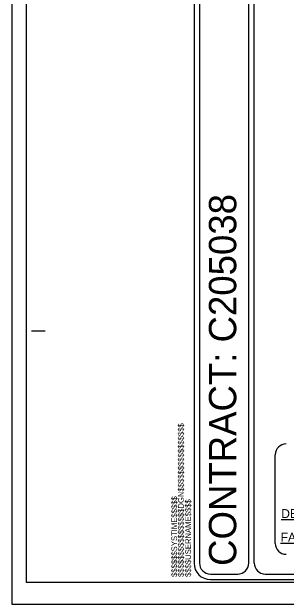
# Model space of a CAD drawing. Extents: x 2046816 to 2049224, y 578750 to 586986.
# Drawn here: x 2047541 to 2047791, y 585891 to 586432 of the extents above; entities that cross this region are included whole.
import ezdxf

# ---------------------------------------------------------------- set-up
doc = ezdxf.new("R2010")
doc.units = 0
for name, color, linetype in [('Sheet Data Field CELL', 7, 'Continuous'), ('Sheet Plan CELL', 7, 'Continuous'), ('Sheet Plot Border Inside CELL', 7, 'Continuous'), ('Sheet Plot Border Outside CELL', 7, 'Continuous'), ('Sheet Title CELL', 7, 'Continuous')]:
    doc.layers.add(name, color=color, linetype=linetype)

msp = doc.modelspace()

# ---------------------------------------------------------------- linework, layer by layer
at = {"layer": 'Sheet Plot Border Inside CELL'}
msp.add_lwpolyline([(2047553.67, 585910.81), (2049219.66, 585910.81), (2049219.66, 586965.81), (2047553.67, 586965.81)], close=True, dxfattribs=at)
at = {"layer": 'Sheet Plot Border Outside CELL'}
msp.add_lwpolyline([(2049224.17, 586985.81), (2047540.67, 586985.81), (2047540.67, 585890.81), (2049224.17, 585890.81)], close=True, dxfattribs=at)
at = {"layer": 'Sheet Title CELL'}
for p, q in [((2047757.16, 585928.33), (2047757.16, 586948.31)), ((2047762.16, 585928.31), (2047762.16, 586948.31)), ((2047558.66, 586140.81), (2047571.16, 586140.83)), ((2047781.37, 585946.39), (2047781.37, 586027.41)), ((2047786.89, 585968.08), (2047942.04, 585968.07)), ((2047786.34, 585946.44), (2047942.59, 585946.44)), ((2047772.18, 585918.31), (2049192.16, 585918.31))]:
    msp.add_line(p, q, dxfattribs=at)
for points in [[(2047707.16, 586948.33), (2047707.16, 585928.31)], [(2047712.18, 586948.33), (2047712.16, 585928.33)], [(2047722.16, 585918.33), (2047747.16, 585918.33)], [(2047722.16, 585913.31), (2049192.16, 585913.31)]]:
    msp.add_lwpolyline(points, dxfattribs=at)
for centre, radius, start, end in [((2047791.37, 586027.41), 10, 90, 180), ((2047791.37, 585946.39), 10, 180, 270), ((2047722.16, 585928.31), 15, 180, 270), ((2047722.16, 585928.33), 10, 179.9993, 270), ((2047747.16, 585928.33), 10, 270, 360), ((2047772.18, 585928.31), 10, 180.0045, 270.0046)]:
    msp.add_arc(centre, radius, start, end, dxfattribs=at)

# ---------------------------------------------------------------- texts
at = {"layer": 'Sheet Data Field CELL'}
for s, p in [('DEVON HOYLE, EI', (2047786.89, 585969.5)), ('FAITH E. JAHNKE, PE', (2047786.34, 585947.86))]:
    msp.add_text(s, height=8.2032, dxfattribs=at).set_placement(p)
at = {"layer": 'Sheet Plan CELL'}
for s, p in [('$$$$$$$$$$$$$$$$DGN$$$$$$$$$$$$$$$$', (2047697.79, 585915.7)), ('$$$$$$SYSTIME$$$$$', (2047691.71, 585915.68)), ('$$$$USERNAME$$$$', (2047704.34, 585915.71))]:
    msp.add_text(s, height=5.2497, rotation=90, dxfattribs=at).set_placement(p)
at = {"layer": 'Sheet Title CELL'}
msp.add_text('CONTRACT: C205038', height=25, rotation=90, dxfattribs=at).set_placement((2047745.78, 585925.79))

doc.saveas('drawing.dxf')
